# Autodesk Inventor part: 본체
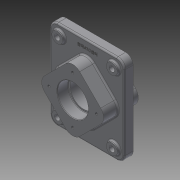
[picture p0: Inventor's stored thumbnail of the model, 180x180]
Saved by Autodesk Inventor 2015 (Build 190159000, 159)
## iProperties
Created: 2026-07
Part Number: 본체
Material: 일반
Document SubType Name: Modeling
Designer: USER
Density: 1 g/cm^3
Appearance: 기본값
Mass: 789.526 g
Surface Area: 957.533 cm^2
Volume: 789.526 cm^3
Author: USER
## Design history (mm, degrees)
sketch "스케치1"
  geometry: L1 (-75, -90)-(75, -90); L2 (75, -90)-(75, 90); L3 (75, 90)-(-75, 90); L4 (-75, 90)-(-75, -90); L5 (-75, -90)-(75, 90); L6 (75, -90)-(-75, 90); 1 further point
  constraints: 12 end point, 2 midpoint, 2 parallel, 1 horizontal, 1 perpendicular
  dimensions: "d0" = 150 distance of L1.start L1.end; "d1" = 180 distance of L1.end L2.end
extrude "돌출1" new body sketch "스케치1" stored distance "d2" = 18; taper "d3" = 0 deg
fillet "모깎기1" dims "d4" = 15
sketch "스케치5"
  geometry: L1 (0, 70.711)-(-70.711, 0); L2 (-70.711, 0)-(0, -70.711); L3 (0, -70.711)-(70.711, 0); L4 (70.711, 0)-(0, 70.711); 1 further point
  constraints: 8 end point, 2 horizontal alignment, 2 parallel, 1 perpendicular, 1 vertical alignment
  dimensions: "d9" = 100 distance of L3.end L1.start; "d10" = 100 distance of L1.start L1.end
extrude "돌출3" join sketch "스케치5" distance "d11" = 29; taper "d13" = 0 deg; dims "d12" = 41, "d14" = 0
fillet "모깎기2" dims "d15" = 20
sketch "스케치9"
  geometry: C1 r 11 at (-55, 70); 1 further point
  constraints: 1 centre point
  dimensions: "d18" = 22 diameter of C1; "d19" = 55 horizontal distance of point (0, 0) C1.centre; "d109" = 70 vertical distance of C1.centre point (0, 0)
extrude "돌출4" join sketch "스케치9" distance "d20" = 5; taper "d21" = 0 deg
sketch "스케치10"
  geometry: C1 r 11 at (0, 0) reference; C2 r 11 at (110, 0) reference; C3 r 11 at (0, -140) reference; C4 r 11 at (110, -140) reference; 1 further point
hole "구멍1" sketch "스케치10" at (0, 0) diameter "d28" = 11; stored, may be unused: countersink angle "d32" = 90 deg, drill point angle "d34" = 118 deg; dims "d29" = 6, "d30" = 4, "d31" = 2, "d33" = 8
sketch "스케치11"
  geometry: 1 further point
hole "구멍2" sketch "스케치11" at (0, 0) diameter "d41" = 54; stored, may be unused: countersink angle "d45" = 90 deg, drill point angle "d47" = 118 deg; dims "d42" = 6, "d43" = 62, "d44" = 22, "d46" = 8
sketch "스케치12"
  geometry: 1 further point
hole "구멍3" sketch "스케치12" at (0, 0) diameter "d48" = 54; stored, may be unused: countersink angle "d52" = 90 deg, drill point angle "d54" = 118 deg; dims "d49" = 6, "d50" = 62, "d51" = 22, "d53" = 8
sketch "스케치15"
  geometry: L1 (0, 0)-(0, -48)
  constraints: 2 end point, 1 vertical
  dimensions: "d74" = 48 distance of L1.start L1.end
hole "구멍6" sketch "스케치15" at (0, -48) diameter "d75" = 4.917; stored, may be unused: countersink angle "d79" = 90 deg, drill point angle "d81" = 118 deg; dims "d76" = 10, "d77" = 62, "d78" = 22, "d80" = 13
sketch "스케치16"
  geometry: L1 (60, 90)-(-60, 90) reference; 2 further points
  constraints: 1 other
  dimensions: "d85" = 15 distance from line of point (1.123, 75) L1
feature "엠보싱1" sketch "스케치16" dims "d0" = 150, "d1" = 180, "d15" = 20, "d86" = 0.5, "d87" = 0
chamfer "모따기1" distance "d88" = 1; stored, may be unused: second distance "d89" = 2, angle "d90" = 45 deg
chamfer "모따기2" distance "d91" = 1; stored, may be unused: second distance "d92" = 2, angle "d93" = 45 deg
fillet "모깎기3" dims "d94" = 3
fillet "모깎기4" dims "d95" = 3
fillet "모깎기5" dims "d96" = 1
fillet "모깎기6" dims "d97" = 3
sketch "스케치17"
  geometry: L1 (0, 0)-(0, 48); C1 r 2.458 at (0, 48) reference
  constraints: 2 end point, 1 vertical
  dimensions: "d98" = 48 distance of L1.start L1.end (derived)
hole "구멍7" sketch "스케치17" at (0, 48) diameter "d99" = 4.917; stored, may be unused: countersink angle "d103" = 90 deg, drill point angle "d105" = 118 deg; dims "d100" = 10, "d101" = 62, "d102" = 22, "d104" = 13
node "솔리드1"
pattern_linear "직사각형 패턴1" dims "d24" = 110
pattern_linear "직사각형 패턴2" dims "d37" = 110
pattern_circular "원형 패턴2" dims angle "d83" = 360 deg
pattern_circular "원형 패턴3" dims angle "d107" = 360 deg
node "투영된 루프1"
node "투영된 루프2"
node "투영된 루프3"
node "투영된 루프4"
